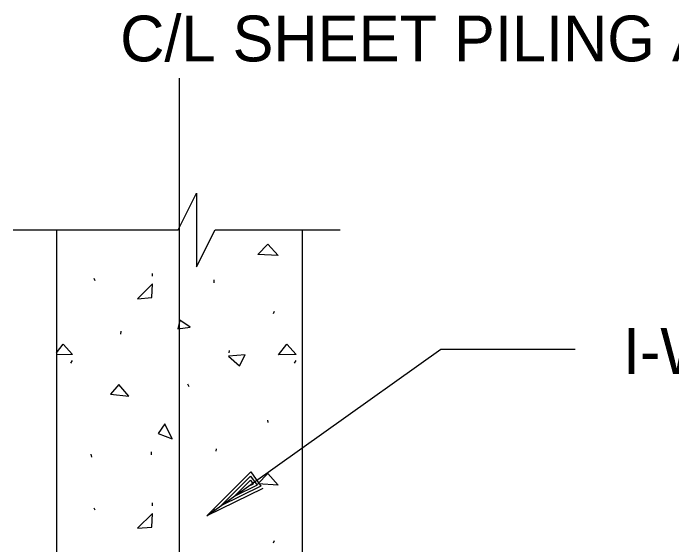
# Model space of a CAD drawing. Extents: x 22411.4 to 22495.4, y 22369.6 to 22415.
# Drawn here: x 22428.783 to 22431.465, y 22396.679 to 22398.846 of the extents above; entities that cross this region are included whole.
import ezdxf

# ---------------------------------------------------------------- set-up
doc = ezdxf.new("R2010")
doc.units = 0
for name, color, linetype in [('Level 1', 7, 'Continuous'), ('Level 2', 7, 'Continuous'), ('Level 4', 7, 'Continuous'), ('Level 7', 7, 'Continuous'), ('Level 8', 7, 'Continuous')]:
    doc.layers.add(name, color=color, linetype=linetype)

msp = doc.modelspace()

# ---------------------------------------------------------------- linework, layer by layer
at = {"layer": 'Level 1'}
for p, q in [((22429.4594, 22389.2676), (22429.4594, 22398.5817)), ((22428.7827, 22397.9625), (22429.4551, 22397.9625)), ((22429.6046, 22397.9625), (22430.1141, 22397.9625)), ((22429.3503, 22397.7736), (22429.3503, 22397.7853)), ((22429.1159, 22397.7553), (22429.1124, 22397.7643)), ((22429.2209, 22397.5378), (22429.2228, 22397.5499)), ((22429.0178, 22397.4201), (22429.0241, 22397.4305)), ((22429.9289, 22397.4201), (22429.9351, 22397.4305)), ((22429.4997, 22397.3226), (22429.4941, 22397.3336)), ((22429.8205, 22397.1774), (22429.8197, 22397.1876)), ((22429.3459, 22397.0457), (22429.3459, 22397.0582)), ((22429.1034, 22397.0357), (22429.0999, 22397.0482)), ((22429.3503, 22396.8384), (22429.3503, 22396.8501)), ((22429.6283, 22396.8378), (22429.6283, 22396.8378)), ((22429.1159, 22396.8201), (22429.1124, 22396.829)), ((22429.6009, 22396.8115), (22429.6009, 22396.824)), ((22429.5718, 22396.7976), (22429.5718, 22396.7976))]:
    msp.add_line(p, q, dxfattribs=at)
for points in [[(22429.4551, 22397.9625), (22429.5296, 22398.1125), (22429.5296, 22397.8128), (22429.6046, 22397.9625)], [(22428.9594, 22397.4622), (22428.9859, 22397.4974)], [(22428.9859, 22397.4974), (22429.0237, 22397.4547)], [(22429.0237, 22397.4547), (22428.9594, 22397.4532)]]:
    msp.add_lwpolyline(points, dxfattribs=at)
for points in [[(22429.3472, 22397.6868), (22429.3503, 22397.7424), (22429.2887, 22397.6822)], [(22429.4528, 22397.5597), (22429.5034, 22397.5661), (22429.4609, 22397.5947)], [(22429.2541, 22397.2851), (22429.2128, 22397.3326), (22429.1797, 22397.2932)], [(22429.373, 22397.1332), (22429.4299, 22397.1111), (22429.3999, 22397.1726)], [(22429.3472, 22396.7515), (22429.3503, 22396.8072), (22429.2887, 22396.747)]]:
    msp.add_lwpolyline(points, close=True, dxfattribs=at)
at = {"layer": 'Level 2'}
for p, q in [((22429.5718, 22396.7976), (22430.5237, 22397.477)), ((22430.5237, 22397.477), (22431.072, 22397.477))]:
    msp.add_line(p, q, dxfattribs=at)
msp.add_lwpolyline([(22429.7988, 22396.9088), (22429.5718, 22396.7976), (22429.7508, 22396.9761), (22429.7918, 22396.9185), (22429.6283, 22396.8378), (22429.7498, 22396.959), (22429.7762, 22396.9221), (22429.6825, 22396.8766), (22429.7489, 22396.942), (22429.7598, 22396.9268), (22429.739, 22396.9169)], dxfattribs=at)
at = {"layer": 'Level 7'}
for p, q in [((22428.9594, 22397.9625), (22428.9594, 22396.1559)), ((22429.9594, 22397.9625), (22429.9594, 22396.1559))]:
    msp.add_line(p, q, dxfattribs=at)
at = {"layer": 'Level 8'}
for p, q in [((22429.6009, 22397.7468), (22429.6009, 22397.7593)), ((22429.8428, 22397.6218), (22429.8474, 22397.6315)), ((22429.6628, 22397.4618), (22429.6637, 22397.4709)), ((22429.6087, 22397.0605), (22429.6103, 22397.0699)), ((22429.8428, 22396.6865), (22429.8474, 22396.6963))]:
    msp.add_line(p, q, dxfattribs=at)
for points in [[(22429.7797, 22397.8624), (22429.8193, 22397.9053), (22429.8618, 22397.8578)], [(22429.8634, 22397.453), (22429.897, 22397.4974), (22429.9347, 22397.4547)], [(22429.6597, 22397.4482), (22429.7041, 22397.4086), (22429.7278, 22397.453)], [(22429.7797, 22396.9272), (22429.8193, 22396.9701), (22429.8618, 22396.9226)]]:
    msp.add_lwpolyline(points, close=True, dxfattribs=at)

# ---------------------------------------------------------------- texts
at = {"layer": 'Level 4'}
for s, height, p in [('C/L SHEET PILING AND I-WALL', 0.186667, (22429.2184, 22398.6497)), ('I-WALL', 0.18667, (22431.2658, 22397.3756))]:
    msp.add_text(s, height=height, dxfattribs=at).set_placement(p)

doc.saveas('drawing.dxf')
